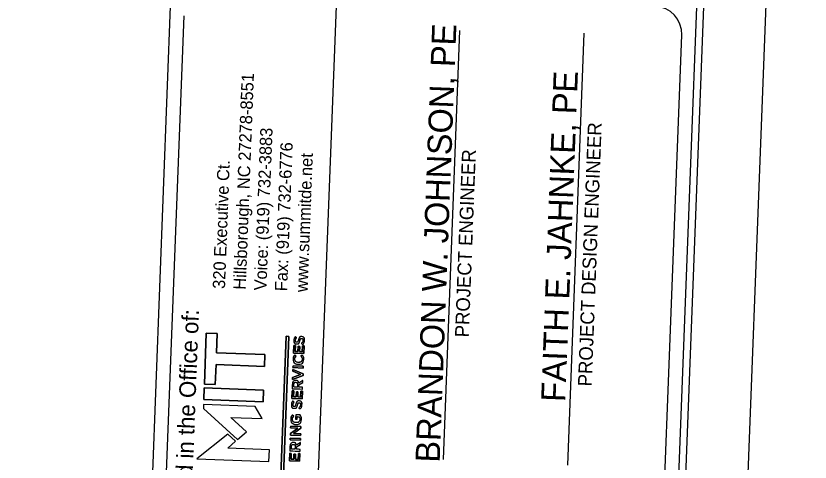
# Model space of a CAD drawing. Extents: x 2094564 to 2100382, y 679033 to 692366.
# Drawn here: x 2098948 to 2100382, y 687593 to 688399 of the extents above; entities that cross this region are included whole.
import ezdxf

# ---------------------------------------------------------------- set-up
doc = ezdxf.new("R2010")
doc.units = 0
for name, color, linetype in [('Old_Level_2', 7, 'Continuous'), ('Prop Horizontal Alignment Direction Label', 7, 'Continuous'), ('Prop Horizontal Alignment Tick Label', 7, 'Continuous'), ('Prop Horizontal Alignment Tick Large', 7, 'Continuous'), ('Scratch_Level_0', 7, 'Continuous')]:
    doc.layers.add(name, color=color, linetype=linetype)

msp = doc.modelspace()

# ---------------------------------------------------------------- linework, layer by layer
at = {"layer": 'Old_Level_2'}
for p, q in [((2099454.7, 687817.7), (2099452.3, 687819.6)), ((2099454.8, 687809.7), (2099454.7, 687809.7)), ((2099463.6, 687819.7), (2099463.5, 687819.7)), ((2099463.7, 687816.4), (2099463.8, 687816.4)), ((2099454.9, 687806.4), (2099454.9, 687806.4)), ((2099463.4, 687807.3), (2099465.6, 687805.3)), ((2099453.9, 687784.6), (2099451.6, 687786.8)), ((2099464.6, 687786.4), (2099462.4, 687784.4)), ((2099457.8, 687773.1), (2099457.7, 687773.1)), ((2099457.7, 687769.7), (2099457.7, 687769.7)), ((2099453.2, 687740.5), (2099453.1, 687740.5)), ((2099453.2, 687737.2), (2099453.2, 687737.2)), ((2099450.3, 687701.5), (2099447.9, 687703.4)), ((2099459.1, 687703.5), (2099459.1, 687703.5)), ((2099459.3, 687700.2), (2099459.3, 687700.2)), ((2099450.3, 687693.4), (2099450.3, 687693.4)), ((2099450.4, 687690.2), (2099450.5, 687690.2)), ((2099458.9, 687691.1), (2099461.2, 687689)), ((2099449.4, 687675.8), (2099447, 687678)), ((2099453.5, 687661), (2099453.5, 687661)), ((2099453.6, 687664.4), (2099453.6, 687664.4)), ((2099448.9, 687628.4), (2099448.8, 687628.4)), ((2099448.9, 687625), (2099448.9, 687625))]:
    msp.add_line(p, q, dxfattribs=at)
for points in [[(2099291.5, 687825.9), (2099311.3, 687825.1), (2099310, 687790.6), (2099397.3, 687787.3), (2099396.4, 687765.9), (2099309.1, 687769.2), (2099307.7, 687733.1), (2099288, 687733.8), (2099291.5, 687825.9)], [(2099288, 687733.8), (2099307.7, 687733.1), (2099309.1, 687769.2), (2099396.4, 687765.9), (2099397.3, 687787.3), (2099310, 687790.6), (2099311.3, 687825.1), (2099291.5, 687825.9), (2099288, 687733.8)], [(2099440.8, 687820.2), (2099420.9, 687302.2), (2099416, 687302.4), (2099435.9, 687820.4), (2099440.8, 687820.2)], [(2099435.9, 687820.4), (2099416, 687302.4), (2099420.9, 687302.2), (2099440.8, 687820.2), (2099435.9, 687820.4)], [(2099449.1, 687789.9), (2099449.7, 687803.6), (2099452.6, 687803.5), (2099452.2, 687793), (2099457, 687792.9), (2099457.4, 687802.2), (2099460.3, 687802), (2099459.9, 687792.7), (2099464.9, 687792.5), (2099465.3, 687803.2), (2099468.2, 687803.1), (2099467.7, 687789.2), (2099449.1, 687789.9)], [(2099467.7, 687789.2), (2099468.2, 687803.1), (2099465.3, 687803.2), (2099464.9, 687792.5), (2099459.9, 687792.7), (2099460.3, 687802), (2099457.4, 687802.2), (2099457, 687792.9), (2099452.2, 687793), (2099452.6, 687803.5), (2099449.7, 687803.6), (2099449.1, 687789.9), (2099467.7, 687789.2)], [(2099448.1, 687763.7), (2099448.3, 687767), (2099466.8, 687766.3), (2099466.7, 687763), (2099448.1, 687763.7)], [(2099466.7, 687763), (2099466.8, 687766.3), (2099448.3, 687767), (2099448.1, 687763.7), (2099466.7, 687763)], [(2099447.3, 687742.3), (2099447.4, 687745.9), (2099461.9, 687751), (2099447.9, 687757.1), (2099448, 687760.6), (2099466.4, 687752.2), (2099466.3, 687749.3), (2099447.3, 687742.3)], [(2099466.3, 687749.3), (2099466.4, 687752.2), (2099448, 687760.6), (2099447.9, 687757.1), (2099461.9, 687751), (2099447.4, 687745.9), (2099447.3, 687742.3), (2099466.3, 687749.3)], [(2099447, 687733.8), (2099446.7, 687725.6), (2099465.2, 687724.9), (2099465.4, 687728.1), (2099458.9, 687728.4), (2099459, 687732.5), (2099465.7, 687736.8), (2099465.8, 687740.6), (2099458.6, 687735.9)], [(2099286.9, 687705.9), (2099287.7, 687727.2), (2099394.8, 687723.1), (2099394, 687701.8), (2099286.9, 687705.9)], [(2099394, 687701.8), (2099394.8, 687723.1), (2099287.7, 687727.2), (2099286.9, 687705.9), (2099394, 687701.8)], [(2099456.2, 687733.3), (2099456, 687728.5), (2099449.8, 687728.7), (2099449.9, 687733.5)], [(2099446, 687707.8), (2099446.5, 687721.6), (2099449.4, 687721.5), (2099449, 687711), (2099453.9, 687710.8), (2099454.2, 687720.1), (2099457.1, 687720), (2099456.8, 687710.7), (2099461.8, 687710.5), (2099462.2, 687721.1), (2099465.1, 687721), (2099464.6, 687707.1), (2099446, 687707.8)], [(2099464.6, 687707.1), (2099465.1, 687721), (2099462.2, 687721.1), (2099461.8, 687710.5), (2099456.8, 687710.7), (2099457.1, 687720), (2099454.2, 687720.1), (2099453.9, 687710.8), (2099449, 687711), (2099449.4, 687721.5), (2099446.5, 687721.6), (2099446, 687707.8), (2099464.6, 687707.1)], [(2099286.3, 687689.6), (2099347.7, 687634.1), (2099364.2, 687647.5), (2099335.7, 687673.6), (2099392.2, 687671.5), (2099379.9, 687693.5), (2099286.6, 687697.1), (2099286.3, 687689.6)], [(2099286.3, 687689.6), (2099347.7, 687634.1), (2099364.2, 687647.5), (2099335.7, 687673.6), (2099392.2, 687671.5), (2099379.9, 687693.5), (2099286.6, 687697.1), (2099286.3, 687689.6)], [(2099460.9, 687678.1), (2099453.1, 687678.4), (2099452.8, 687670.5), (2099455.6, 687670.4), (2099455.8, 687675.1), (2099459.3, 687675)], [(2099443.5, 687641.8), (2099443.6, 687644.8), (2099456.8, 687654.2), (2099443.9, 687654.7), (2099444.1, 687657.9), (2099462.6, 687657.2), (2099462.5, 687654.5), (2099448.9, 687644.8), (2099462.2, 687644.3), (2099462, 687641.1), (2099443.5, 687641.8)], [(2099462, 687641.1), (2099462.2, 687644.3), (2099448.9, 687644.8), (2099462.5, 687654.5), (2099462.6, 687657.2), (2099444.1, 687657.9), (2099443.9, 687654.7), (2099456.8, 687654.2), (2099443.6, 687644.8), (2099443.5, 687641.8), (2099462, 687641.1)], [(2099274.3, 687598.8), (2099404.7, 687593.8), (2099405.5, 687615.1), (2099330.3, 687618), (2099344.3, 687630.7), (2099330.5, 687643.7), (2099274.3, 687598.8)], [(2099274.3, 687598.8), (2099404.7, 687593.8), (2099405.5, 687615.1), (2099330.3, 687618), (2099344.3, 687630.7), (2099330.5, 687643.7), (2099274.3, 687598.8)], [(2099442.7, 687621.7), (2099442.4, 687613.4), (2099460.9, 687612.7), (2099461.1, 687616), (2099454.6, 687616.2), (2099454.7, 687620.3), (2099461.4, 687624.6), (2099461.5, 687628.5), (2099454.3, 687623.7)], [(2099443.1, 687633.3), (2099443.3, 687636.5), (2099461.8, 687635.8), (2099461.7, 687632.6), (2099443.1, 687633.3)], [(2099461.7, 687632.6), (2099461.8, 687635.8), (2099443.3, 687636.5), (2099443.1, 687633.3), (2099461.7, 687632.6)], [(2099441.7, 687595.2), (2099442.2, 687608.9), (2099445.1, 687608.8), (2099444.7, 687598.3), (2099449.5, 687598.1), (2099449.9, 687607.4), (2099452.8, 687607.3), (2099452.5, 687598), (2099457.4, 687597.8), (2099457.9, 687608.4), (2099460.8, 687608.3), (2099460.2, 687594.4), (2099441.7, 687595.2)], [(2099460.2, 687594.4), (2099460.8, 687608.3), (2099457.9, 687608.4), (2099457.4, 687597.8), (2099452.5, 687598), (2099452.8, 687607.3), (2099449.9, 687607.4), (2099449.5, 687598.1), (2099444.7, 687598.3), (2099445.1, 687608.8), (2099442.2, 687608.9), (2099441.7, 687595.2), (2099460.2, 687594.4)], [(2099451.9, 687621.1), (2099451.7, 687616.3), (2099445.5, 687616.6), (2099445.6, 687621.3)]]:
    msp.add_lwpolyline(points, dxfattribs=at)
for points, degree in [([(2099465.6, 687805.3), (2099465.6, 687805.3), (2099463.4, 687807.3), (2099463.4, 687807.3), (2099465, 687809), (2099465.9, 687810.8), (2099466, 687813.1), (2099466.1, 687815.1), (2099465.2, 687816.4), (2099463.8, 687816.4), (2099463.8, 687816.4), (2099463.7, 687816.4), (2099463.7, 687816.4), (2099462.4, 687816.5), (2099461.7, 687815.8), (2099460.7, 687812.4), (2099459.6, 687808.5), (2099458.4, 687806.3), (2099454.9, 687806.4), (2099454.9, 687806.4), (2099454.9, 687806.4), (2099454.9, 687806.4), (2099451.7, 687806.5), (2099449.6, 687809.3), (2099449.7, 687812.9), (2099449.9, 687815.6), (2099450.8, 687817.8), (2099452.3, 687819.6), (2099452.3, 687819.6), (2099454.7, 687817.7), (2099454.7, 687817.7), (2099453.4, 687816.1), (2099452.7, 687814.5), (2099452.6, 687812.8), (2099452.6, 687810.9), (2099453.5, 687809.7), (2099454.7, 687809.7), (2099454.7, 687809.7), (2099454.8, 687809.7), (2099454.8, 687809.7), (2099456.2, 687809.6), (2099456.9, 687810.4), (2099457.9, 687814), (2099459, 687817.9), (2099460.5, 687819.8), (2099463.5, 687819.7), (2099463.5, 687819.7), (2099463.6, 687819.7), (2099463.6, 687819.7), (2099467.1, 687819.6), (2099469, 687816.8), (2099468.9, 687812.9), (2099468.8, 687810), (2099467.7, 687807.4), (2099465.6, 687805.3)], 3), ([(2099452.3, 687819.6), (2099450.8, 687817.8), (2099449.9, 687815.6), (2099449.7, 687812.9), (2099449.6, 687809.3), (2099451.7, 687806.5), (2099454.9, 687806.4)], 3), ([(2099454.7, 687809.7), (2099453.5, 687809.7), (2099452.6, 687810.9), (2099452.6, 687812.8), (2099452.7, 687814.5), (2099453.4, 687816.1), (2099454.7, 687817.7)], 3), ([(2099463.5, 687819.7), (2099460.5, 687819.8), (2099459, 687817.9), (2099457.9, 687814), (2099456.9, 687810.4), (2099456.2, 687809.6), (2099454.8, 687809.7)], 3), ([(2099454.9, 687806.4), (2099458.4, 687806.3), (2099459.6, 687808.5), (2099460.7, 687812.4), (2099461.7, 687815.8), (2099462.4, 687816.5), (2099463.7, 687816.4)], 3), ([(2099463.8, 687816.4), (2099465.2, 687816.4), (2099466.1, 687815.1), (2099466, 687813.1), (2099465.9, 687810.8), (2099465, 687809), (2099463.4, 687807.3)], 3), ([(2099465.6, 687805.3), (2099467.7, 687807.4), (2099468.8, 687810), (2099468.9, 687812.9), (2099469, 687816.8), (2099467.1, 687819.6), (2099463.6, 687819.7)], 3), ([(2099457.7, 687769.7), (2099457.7, 687769.7), (2099457.7, 687769.7), (2099457.7, 687769.7), (2099452.4, 687769.9), (2099448.2, 687774), (2099448.4, 687779.6), (2099448.5, 687783), (2099449.8, 687785.1), (2099451.6, 687786.8), (2099451.6, 687786.8), (2099453.9, 687784.6), (2099453.9, 687784.6), (2099452.5, 687783.2), (2099451.5, 687781.6), (2099451.4, 687779.5), (2099451.3, 687776), (2099454.1, 687773.3), (2099457.7, 687773.1), (2099457.7, 687773.1), (2099457.8, 687773.1), (2099457.8, 687773.1), (2099461.4, 687773), (2099464.5, 687775.4), (2099464.6, 687779), (2099464.7, 687781.3), (2099463.8, 687782.8), (2099462.4, 687784.4), (2099462.4, 687784.4), (2099464.6, 687786.4), (2099464.6, 687786.4), (2099466.6, 687784.4), (2099467.8, 687782.2), (2099467.6, 687778.8), (2099467.4, 687773.4), (2099463, 687769.5), (2099457.7, 687769.7)], 3), ([(2099451.6, 687786.8), (2099449.8, 687785.1), (2099448.5, 687783), (2099448.4, 687779.6), (2099448.2, 687774), (2099452.4, 687769.9), (2099457.7, 687769.7)], 3), ([(2099457.7, 687773.1), (2099454.1, 687773.3), (2099451.3, 687776), (2099451.4, 687779.5), (2099451.5, 687781.6), (2099452.5, 687783.2), (2099453.9, 687784.6)], 3), ([(2099457.7, 687769.7), (2099463, 687769.5), (2099467.4, 687773.4), (2099467.6, 687778.8), (2099467.8, 687782.2), (2099466.6, 687784.4), (2099464.6, 687786.4)], 3), ([(2099462.4, 687784.4), (2099463.8, 687782.8), (2099464.7, 687781.3), (2099464.6, 687779), (2099464.5, 687775.4), (2099461.4, 687773), (2099457.8, 687773.1)], 3), ([(2099446.7, 687725.6), (2099446.7, 687725.6), (2099447, 687733.8), (2099447, 687733.8), (2099447.1, 687736.2), (2099447.8, 687738), (2099449, 687739.1), (2099450.1, 687740.1), (2099451.5, 687740.6), (2099453.1, 687740.5), (2099453.1, 687740.5), (2099453.2, 687740.5), (2099453.2, 687740.5), (2099456.2, 687740.4), (2099458, 687738.5), (2099458.6, 687735.9), (2099458.6, 687735.9), (2099465.8, 687740.6), (2099465.8, 687740.6), (2099465.8, 687740.6), (2099465.7, 687736.8), (2099465.7, 687736.8), (2099465.7, 687736.8), (2099459, 687732.5), (2099459, 687732.5), (2099459, 687732.5), (2099458.9, 687728.4), (2099458.9, 687728.4), (2099458.9, 687728.4), (2099465.4, 687728.1), (2099465.4, 687728.1), (2099465.4, 687728.1), (2099465.2, 687724.9), (2099465.2, 687724.9), (2099465.2, 687724.9), (2099446.7, 687725.6), (2099446.7, 687725.6)], 3), ([(2099453.1, 687740.5), (2099451.5, 687740.6), (2099450.1, 687740.1), (2099449, 687739.1), (2099447.8, 687738), (2099447.1, 687736.2), (2099447, 687733.8)], 3), ([(2099458.6, 687735.9), (2099458, 687738.5), (2099456.2, 687740.4), (2099453.2, 687740.5)], 2), ([(2099456.2, 687733.3), (2099456.3, 687735.6), (2099455.1, 687737.1), (2099453.2, 687737.2), (2099453.2, 687737.2), (2099453.2, 687737.2), (2099453.2, 687737.2), (2099451.2, 687737.3), (2099450, 687735.9), (2099449.9, 687733.5), (2099449.9, 687733.5), (2099449.8, 687728.7), (2099449.8, 687728.7), (2099449.8, 687728.7), (2099456, 687728.5), (2099456, 687728.5), (2099456, 687728.5), (2099456.2, 687733.3), (2099456.2, 687733.3)], 3), ([(2099449.9, 687733.5), (2099450, 687735.9), (2099451.2, 687737.3), (2099453.2, 687737.2)], 2), ([(2099453.2, 687737.2), (2099455.1, 687737.1), (2099456.3, 687735.6), (2099456.2, 687733.3)], 2), ([(2099461.2, 687689), (2099461.2, 687689), (2099458.9, 687691.1), (2099458.9, 687691.1), (2099460.5, 687692.8), (2099461.4, 687694.6), (2099461.5, 687696.8), (2099461.6, 687698.9), (2099460.7, 687700.2), (2099459.3, 687700.2), (2099459.3, 687700.2), (2099459.3, 687700.2), (2099459.3, 687700.2), (2099457.9, 687700.3), (2099457.2, 687699.5), (2099456.3, 687696.1), (2099455.2, 687692.2), (2099453.9, 687690), (2099450.5, 687690.2), (2099450.5, 687690.2), (2099450.4, 687690.2), (2099450.4, 687690.2), (2099447.3, 687690.3), (2099445.2, 687693), (2099445.3, 687696.7), (2099445.4, 687699.4), (2099446.3, 687701.5), (2099447.9, 687703.4), (2099447.9, 687703.4), (2099450.3, 687701.5), (2099450.3, 687701.5), (2099449, 687699.9), (2099448.2, 687698.2), (2099448.2, 687696.6), (2099448.1, 687694.6), (2099449, 687693.5), (2099450.3, 687693.4), (2099450.3, 687693.4), (2099450.3, 687693.4), (2099450.3, 687693.4), (2099451.8, 687693.4), (2099452.4, 687694.2), (2099453.4, 687697.8), (2099454.5, 687701.6), (2099456, 687703.6), (2099459.1, 687703.5), (2099459.1, 687703.5), (2099459.1, 687703.5), (2099459.1, 687703.5), (2099462.6, 687703.4), (2099464.6, 687700.5), (2099464.4, 687696.6), (2099464.3, 687693.8), (2099463.2, 687691.2), (2099461.2, 687689)], 3), ([(2099447.9, 687703.4), (2099446.3, 687701.5), (2099445.4, 687699.4), (2099445.3, 687696.7), (2099445.2, 687693), (2099447.3, 687690.3), (2099450.4, 687690.2)], 3), ([(2099450.3, 687693.4), (2099449, 687693.5), (2099448.1, 687694.6), (2099448.2, 687696.6), (2099448.2, 687698.2), (2099449, 687699.9), (2099450.3, 687701.5)], 3), ([(2099459.1, 687703.5), (2099456, 687703.6), (2099454.5, 687701.6), (2099453.4, 687697.8), (2099452.4, 687694.2), (2099451.8, 687693.4), (2099450.3, 687693.4)], 3), ([(2099450.5, 687690.2), (2099453.9, 687690), (2099455.2, 687692.2), (2099456.3, 687696.1), (2099457.2, 687699.5), (2099457.9, 687700.3), (2099459.3, 687700.2)], 3), ([(2099459.3, 687700.2), (2099460.7, 687700.2), (2099461.6, 687698.9), (2099461.5, 687696.8), (2099461.4, 687694.6), (2099460.5, 687692.8), (2099458.9, 687691.1)], 3), ([(2099461.2, 687689), (2099463.2, 687691.2), (2099464.3, 687693.8), (2099464.4, 687696.6), (2099464.6, 687700.5), (2099462.6, 687703.4), (2099459.1, 687703.5)], 3), ([(2099453.5, 687661), (2099453.5, 687661), (2099453.5, 687661), (2099453.5, 687661), (2099448.3, 687661.2), (2099444, 687665.3), (2099444.2, 687670.9), (2099444.4, 687674.2), (2099445.4, 687676.1), (2099447, 687678), (2099447, 687678), (2099449.4, 687675.8), (2099449.4, 687675.8), (2099448.2, 687674.4), (2099447.3, 687673), (2099447.2, 687670.7), (2099447.1, 687667.3), (2099450, 687664.5), (2099453.6, 687664.4), (2099453.6, 687664.4), (2099453.6, 687664.4), (2099453.6, 687664.4), (2099457.4, 687664.3), (2099460.4, 687666.7), (2099460.5, 687670.5), (2099460.6, 687672.2), (2099460.1, 687673.8), (2099459.3, 687675), (2099459.3, 687675), (2099455.8, 687675.1), (2099455.8, 687675.1), (2099455.8, 687675.1), (2099455.6, 687670.4), (2099455.6, 687670.4), (2099455.6, 687670.4), (2099452.8, 687670.5), (2099452.8, 687670.5), (2099452.8, 687670.5), (2099453.1, 687678.4), (2099453.1, 687678.4), (2099453.1, 687678.4), (2099460.9, 687678.1), (2099460.9, 687678.1), (2099462.4, 687676.2), (2099463.6, 687673.5), (2099463.5, 687670.2), (2099463.2, 687664.4), (2099459, 687660.8), (2099453.5, 687661)], 3), ([(2099447, 687678), (2099445.4, 687676.1), (2099444.4, 687674.2), (2099444.2, 687670.9), (2099444, 687665.3), (2099448.3, 687661.2), (2099453.5, 687661)], 3), ([(2099453.6, 687664.4), (2099450, 687664.5), (2099447.1, 687667.3), (2099447.2, 687670.7), (2099447.3, 687673), (2099448.2, 687674.4), (2099449.4, 687675.8)], 3), ([(2099453.5, 687661), (2099459, 687660.8), (2099463.2, 687664.4), (2099463.5, 687670.2), (2099463.6, 687673.5), (2099462.4, 687676.2), (2099460.9, 687678.1)], 3), ([(2099459.3, 687675), (2099460.1, 687673.8), (2099460.6, 687672.2), (2099460.5, 687670.5), (2099460.4, 687666.7), (2099457.4, 687664.3), (2099453.6, 687664.4)], 3), ([(2099442.4, 687613.4), (2099442.4, 687613.4), (2099442.7, 687621.7), (2099442.7, 687621.7), (2099442.8, 687624), (2099443.5, 687625.8), (2099444.7, 687627), (2099445.8, 687627.9), (2099447.2, 687628.4), (2099448.8, 687628.4), (2099448.8, 687628.4), (2099448.9, 687628.4), (2099448.9, 687628.4), (2099451.9, 687628.2), (2099453.7, 687626.3), (2099454.3, 687623.7), (2099454.3, 687623.7), (2099461.5, 687628.5), (2099461.5, 687628.5), (2099461.5, 687628.5), (2099461.4, 687624.6), (2099461.4, 687624.6), (2099461.4, 687624.6), (2099454.7, 687620.3), (2099454.7, 687620.3), (2099454.7, 687620.3), (2099454.6, 687616.2), (2099454.6, 687616.2), (2099454.6, 687616.2), (2099461.1, 687616), (2099461.1, 687616), (2099461.1, 687616), (2099460.9, 687612.7), (2099460.9, 687612.7), (2099460.9, 687612.7), (2099442.4, 687613.4), (2099442.4, 687613.4)], 3), ([(2099448.8, 687628.4), (2099447.2, 687628.4), (2099445.8, 687627.9), (2099444.7, 687627), (2099443.5, 687625.8), (2099442.8, 687624), (2099442.7, 687621.7)], 3), ([(2099451.9, 687621.1), (2099452, 687623.4), (2099450.8, 687625), (2099448.9, 687625), (2099448.9, 687625), (2099448.9, 687625), (2099448.9, 687625), (2099446.9, 687625.1), (2099445.7, 687623.7), (2099445.6, 687621.3), (2099445.6, 687621.3), (2099445.5, 687616.6), (2099445.5, 687616.6), (2099445.5, 687616.6), (2099451.7, 687616.3), (2099451.7, 687616.3), (2099451.7, 687616.3), (2099451.9, 687621.1), (2099451.9, 687621.1)], 3), ([(2099445.6, 687621.3), (2099445.7, 687623.7), (2099446.9, 687625.1), (2099448.9, 687625)], 2), ([(2099454.3, 687623.7), (2099453.7, 687626.3), (2099451.9, 687628.2), (2099448.9, 687628.4)], 2), ([(2099448.9, 687625), (2099450.8, 687625), (2099452, 687623.4), (2099451.9, 687621.1)], 2)]:
    msp.add_open_spline(points, degree=degree, dxfattribs=at)
at = {"layer": 'Prop Horizontal Alignment Direction Label'}
for p, q in [((2099030, 683278.9), (2099302.1, 690373.6)), ((2099526.9, 688438.6), (2099468.4, 686914.7)), ((2099196.8, 686975.2), (2099251.4, 688399.1)), ((2099719.8, 687597.9), (2099749.6, 688373)), ((2099944.5, 687587.5), (2099974.5, 688368.2))]:
    msp.add_line(p, q, dxfattribs=at)
for points in [[(2099968.8, 682967.7), (2100252.4, 690362.2)], [(2100096.1, 686940.7), (2100150.8, 688364.6)]]:
    msp.add_lwpolyline(points, dxfattribs=at)
msp.add_arc((2100100.5, 688366.6), 50, 357.8037, 87.8037, dxfattribs=at)
at = {"layer": 'Prop Horizontal Alignment Tick Label'}
msp.add_lwpolyline([(2099950.1, 682147.8), (2100269.5, 690474.2), (2094997.8, 690676.3), (2094678.5, 682349.9)], close=True, dxfattribs=at)
at = {"layer": 'Prop Horizontal Alignment Tick Large'}
msp.add_lwpolyline([(2094886.5, 690703.1), (2094563.9, 682289.3), (2100059.8, 682078.5), (2100382.4, 690492.3)], close=True, dxfattribs=at)

# ---------------------------------------------------------------- texts
at = {"layer": 'Old_Level_2'}
for s, p in [('Hillsborough, NC 27278-8551 ', (2099362.7, 687904.1)), ('Voice: (919) 732-3883 ', (2099400.1, 687902.7)), ('Fax: (919) 732-6776 ', (2099437.5, 687901.3)), ('www.summitde.net', (2099474.5, 687899.8)), ('320 Executive Ct.', (2099325.2, 687905.6))]:
    msp.add_text(s, height=22.233, rotation=87.8037, dxfattribs=at).set_placement(p)
at = {"layer": 'Prop Horizontal Alignment Direction Label'}
for s, height, p in [('PROJECT DESIGN ENGINEER', 24.997, (2099987.8, 687729.4)), ('PROJECT ENGINEER', 24.997, (2099765.7, 687818)), ('Prepared in the Office of:', 29.997, (2099261.3, 687423))]:
    msp.add_text(s, height=height, rotation=87.8037, dxfattribs=at).set_placement(p)
at = {"layer": 'Scratch_Level_0'}
for s, p in [('BRANDON W. JOHNSON, PE', (2099713.1, 687591.6)), ('FAITH E. JAHNKE, PE', (2099940.1, 687701.2))]:
    msp.add_text(s, height=43.75, rotation=87.8037, dxfattribs=at).set_placement(p)

doc.saveas('drawing.dxf')
